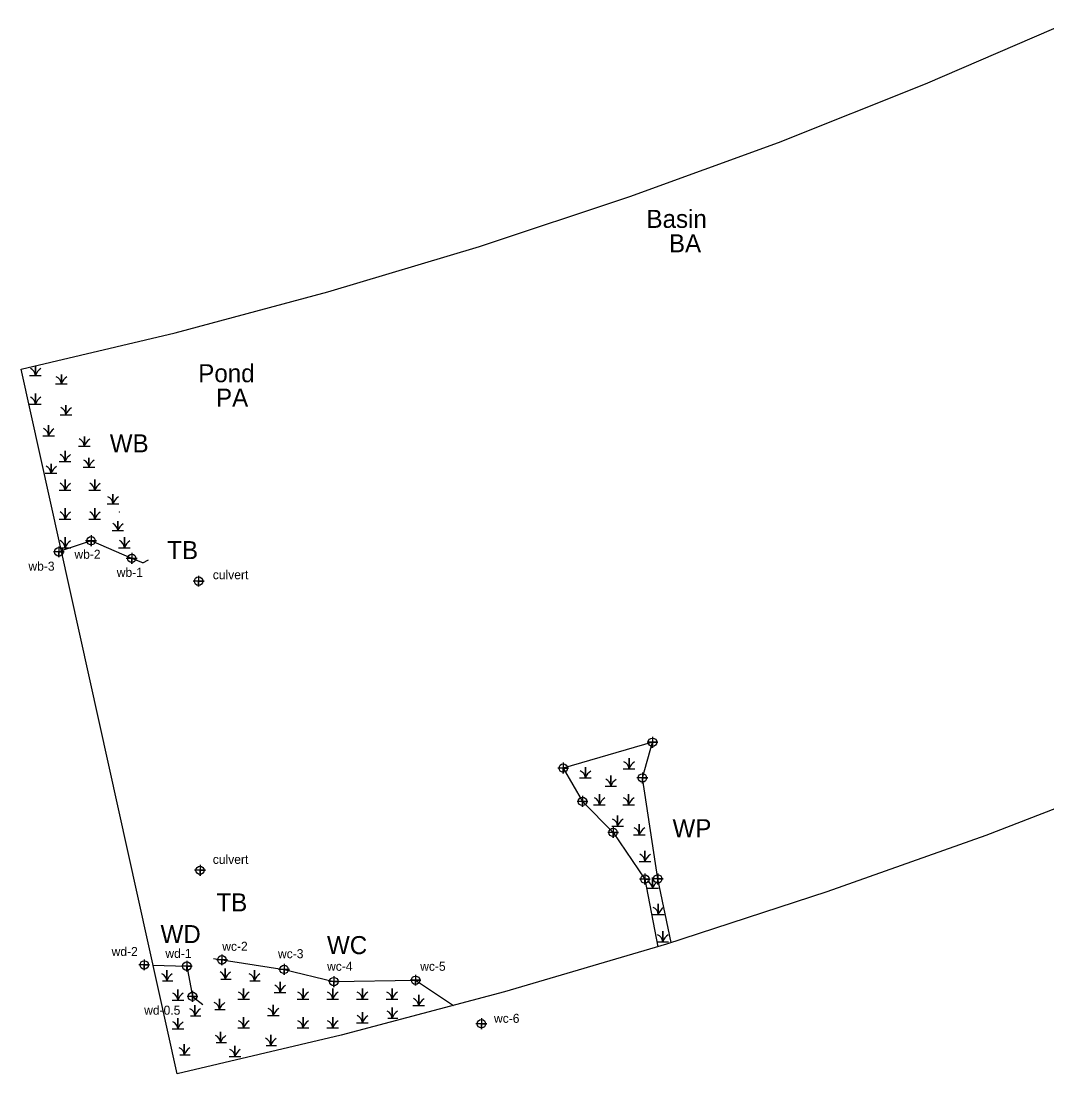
# Model space of a CAD drawing. Extents: x 2174810 to 2196950, y 76168 to 88270.
# Drawn here: x 2174810 to 2175379, y 76168 to 76752 of the extents above; entities that cross this region are included whole.
import ezdxf

# ---------------------------------------------------------------- set-up
doc = ezdxf.new("R2010")
doc.units = 0
for name, color, linetype in [('Default', 7, 'Continuous'), ('Exist Environmental Wetland Boundary', 7, 'Continuous'), ('Exist Environmental Wetland Boundary Cogo Number', 7, 'Continuous'), ('Exist Environmental Wetland Boundary Cogo Point CELL', 7, 'Continuous'), ('Exist Environmental Wetland Boundary Text', 7, 'Continuous'), ('Exist Hydro Jurisdictional Stream or Body of Water Mitigable Text', 7, 'Continuous'), ('Exist Hydro Jurisdictional Stream or Body of Water NonMitigable Cogo Number', 7, 'Continuous'), ('Exist Hydro Jurisdictional Stream or Body of Water NonMitigable Cogo Point CELL', 7, 'Continuous'), ('Exist Hydro Jurisdictional Stream or Body of Water NonMitigable Text', 7, 'Continuous'), ('Exist Hydro Swamp or Marsh', 7, 'Continuous')]:
    doc.layers.add(name, color=color, linetype=linetype)

msp = doc.modelspace()

# ---------------------------------------------------------------- linework, layer by layer
at = {"layer": 'Default'}
msp.add_lwpolyline([(2175432.71, 76334.2), (2175345.43, 76300.42), (2175257.26, 76269.05), (2175168.26, 76240.12), (2175078.5, 76213.66), (2174988.04, 76189.67), (2174896.96, 76168.18), (2174810.48, 76558.72), (2174895.85, 76578.94), (2174980.6, 76601.65), (2175064.65, 76626.82), (2175147.93, 76654.45), (2175230.37, 76684.5), (2175311.89, 76716.94), (2175392.42, 76751.76)], dxfattribs=at)
at = {"layer": 'Exist Environmental Wetland Boundary'}
for p, q in [((2174849.27, 76463.72), (2174832.77, 76458.03)), ((2174871.83, 76453.96), (2174849.27, 76463.72)), ((2174878, 76451.47), (2174871.83, 76453.96)), ((2174878, 76451.47), (2174881.16, 76453.17)), ((2174883.61, 76228.47), (2174902.38, 76227.91)), ((2174902.38, 76227.91), (2174905.52, 76211.18)), ((2174917.24, 76232.1), (2174956.29, 76226.14)), ((2174956.29, 76226.14), (2174983.88, 76219.34)), ((2174983.88, 76219.34), (2175029.2, 76220.11)), ((2175029.2, 76220.11), (2175050.3, 76206.18)), ((2174905.52, 76211.18), (2174911.31, 76206.67))]:
    msp.add_line(p, q, dxfattribs=at)
msp.add_lwpolyline([(2175170.83, 76240.96), (2175163.47, 76276.25), (2175154.94, 76332.25), (2175160.56, 76352), (2175111.07, 76337.73), (2175121.75, 76319.26), (2175138.71, 76302.08), (2175156.34, 76276.19), (2175163.49, 76238.72)], dxfattribs=at)
at = {"layer": 'Exist Environmental Wetland Boundary Cogo Point CELL'}
for points in [[(2174849.27, 76466.72), (2174849.27, 76460.72), (2174849.27, 76463.72), (2174852.27, 76463.72), (2174846.27, 76463.72)], [(2174831.41, 76460.56), (2174831.41, 76454.56), (2174831.41, 76457.56), (2174834.41, 76457.56), (2174828.41, 76457.56)], [(2174871.83, 76456.96), (2174871.83, 76450.96), (2174871.83, 76453.96), (2174874.83, 76453.96), (2174868.83, 76453.96)], [(2175160.56, 76355), (2175160.56, 76349), (2175160.56, 76352), (2175163.56, 76352), (2175157.56, 76352)], [(2175111.07, 76340.73), (2175111.07, 76334.73), (2175111.07, 76337.73), (2175114.07, 76337.73), (2175108.07, 76337.73)], [(2175154.94, 76335.25), (2175154.94, 76329.25), (2175154.94, 76332.25), (2175157.94, 76332.25), (2175151.94, 76332.25)], [(2175121.75, 76322.26), (2175121.75, 76316.26), (2175121.75, 76319.26), (2175124.75, 76319.26), (2175118.75, 76319.26)], [(2175138.71, 76305.08), (2175138.71, 76299.08), (2175138.71, 76302.08), (2175141.71, 76302.08), (2175135.71, 76302.08)], [(2175156.34, 76279.19), (2175156.34, 76273.19), (2175156.34, 76276.19), (2175159.34, 76276.19), (2175153.34, 76276.19)], [(2175163.47, 76279.25), (2175163.47, 76273.25), (2175163.47, 76276.25), (2175166.47, 76276.25), (2175160.47, 76276.25)], [(2174921.86, 76234.4), (2174921.86, 76228.4), (2174921.86, 76231.4), (2174924.86, 76231.4), (2174918.86, 76231.4)], [(2174878.77, 76231.62), (2174878.77, 76225.62), (2174878.77, 76228.62), (2174881.77, 76228.62), (2174875.77, 76228.62)], [(2174902.38, 76230.91), (2174902.38, 76224.91), (2174902.38, 76227.91), (2174905.38, 76227.91), (2174899.38, 76227.91)], [(2174956.29, 76229.14), (2174956.29, 76223.14), (2174956.29, 76226.14), (2174959.29, 76226.14), (2174953.29, 76226.14)], [(2174983.88, 76222.34), (2174983.88, 76216.34), (2174983.88, 76219.34), (2174986.88, 76219.34), (2174980.88, 76219.34)], [(2175029.2, 76223.11), (2175029.2, 76217.11), (2175029.2, 76220.11), (2175032.2, 76220.11), (2175026.2, 76220.11)], [(2174905.52, 76214.18), (2174905.52, 76208.18), (2174905.52, 76211.18), (2174908.52, 76211.18), (2174902.52, 76211.18)], [(2175065.69, 76199.02), (2175065.69, 76193.02), (2175065.69, 76196.02), (2175068.69, 76196.02), (2175062.69, 76196.02)]]:
    msp.add_lwpolyline(points, dxfattribs=at)
for centre in [(2174849.27, 76463.72), (2174831.41, 76457.56), (2174871.83, 76453.96), (2175160.56, 76352), (2175111.07, 76337.73), (2175154.94, 76332.25), (2175121.75, 76319.26), (2175138.71, 76302.08), (2175156.34, 76276.19), (2175163.47, 76276.25), (2174921.86, 76231.4), (2174878.77, 76228.62), (2174902.38, 76227.91), (2174956.29, 76226.14), (2174983.88, 76219.34), (2175029.2, 76220.11), (2174905.52, 76211.18), (2175065.69, 76196.02)]:
    msp.add_circle(centre, 2.34, dxfattribs=at)
at = {"layer": 'Exist Hydro Jurisdictional Stream or Body of Water NonMitigable Cogo Point CELL'}
for points in [[(2174908.92, 76444.3), (2174908.92, 76438.3), (2174908.92, 76441.3), (2174911.92, 76441.3), (2174905.92, 76441.3)], [(2174909.69, 76284.04), (2174909.69, 76278.04), (2174909.69, 76281.04), (2174912.69, 76281.04), (2174906.69, 76281.04)]]:
    msp.add_lwpolyline(points, dxfattribs=at)
for centre in [(2174908.92, 76441.3), (2174909.69, 76281.04)]:
    msp.add_circle(centre, 2.34, dxfattribs=at)
at = {"layer": 'Exist Hydro Swamp or Marsh'}
for p, q in [((2174921.07, 76185.57), (2174921.07, 76191.49)), ((2174921.07, 76191.49), (2174921.07, 76185.57)), ((2174918.61, 76185.57), (2174921.07, 76185.57)), ((2174921.07, 76185.57), (2174924.29, 76185.57))]:
    msp.add_line(p, q, dxfattribs=at)
for points in [[(2174815.23, 76555.35), (2174818.46, 76555.35), (2174818.46, 76560.61)], [(2174818.46, 76560.61), (2174818.46, 76555.35), (2174821.68, 76555.35)], [(2174829.62, 76550.66), (2174832.85, 76550.66), (2174832.85, 76555.92)], [(2174832.85, 76555.92), (2174832.85, 76550.66), (2174836.07, 76550.66)], [(2174815.23, 76539.43), (2174818.46, 76539.43), (2174818.46, 76545.35), (2174818.46, 76539.43), (2174821.68, 76539.43)], [(2174832.13, 76533.59), (2174835.36, 76533.59), (2174835.36, 76538.85)], [(2174835.36, 76538.85), (2174835.36, 76533.59), (2174838.58, 76533.59)], [(2174822.51, 76521.93), (2174825.73, 76521.93), (2174825.73, 76527.85), (2174825.73, 76521.93), (2174828.96, 76521.93)], [(2174842.34, 76516.18), (2174845.56, 76516.18), (2174845.56, 76521.44)], [(2174845.56, 76521.44), (2174845.56, 76516.18), (2174848.79, 76516.18)], [(2174831.68, 76507.59), (2174834.91, 76507.59), (2174834.91, 76513.51), (2174834.91, 76507.59), (2174838.14, 76507.59)], [(2174844.84, 76504.47), (2174848.07, 76504.47), (2174848.07, 76509.73)], [(2174848.07, 76509.73), (2174848.07, 76504.47), (2174851.3, 76504.47)], [(2174823.93, 76501.12), (2174827.16, 76501.12), (2174827.16, 76506.38)], [(2174827.16, 76506.38), (2174827.16, 76501.12), (2174830.38, 76501.12)], [(2174831.68, 76491.68), (2174834.91, 76491.68), (2174834.91, 76497.59), (2174834.91, 76491.68), (2174838.14, 76491.68)], [(2174848.14, 76491.68), (2174851.36, 76491.68), (2174851.36, 76497.59), (2174851.36, 76491.68), (2174854.59, 76491.68)], [(2174858.23, 76484.21), (2174861.45, 76484.21), (2174861.45, 76489.47)], [(2174861.45, 76489.47), (2174861.45, 76484.21), (2174864.68, 76484.21)], [(2174831.68, 76475.76), (2174834.91, 76475.76), (2174834.91, 76481.68), (2174834.91, 76475.76), (2174838.14, 76475.76)], [(2174848.14, 76475.76), (2174851.36, 76475.76), (2174851.36, 76481.68), (2174851.36, 76475.76), (2174854.59, 76475.76)], [(2174860.91, 76469.32), (2174864.13, 76469.32), (2174864.13, 76474.58)], [(2174864.13, 76474.58), (2174864.13, 76469.32), (2174867.36, 76469.32)], [(2174832.37, 76459.84), (2174834.91, 76459.84), (2174834.91, 76465.76), (2174834.91, 76459.84), (2174838.04, 76459.84)], [(2174864.59, 76459.84), (2174867.81, 76459.84), (2174867.81, 76465.76), (2174867.81, 76459.84), (2174871.04, 76459.84)], [(2175120.15, 76332.25), (2175123.38, 76332.25), (2175123.38, 76338.17), (2175123.38, 76332.25), (2175126.6, 76332.25)], [(2175144.32, 76337.3), (2175147.55, 76337.3), (2175147.55, 76343.22), (2175147.55, 76337.3), (2175150.77, 76337.3)], [(2175134.23, 76327.63), (2175137.46, 76327.63), (2175137.46, 76333.55), (2175137.46, 76327.63), (2175140.68, 76327.63)], [(2175127.93, 76317.33), (2175131.15, 76317.33), (2175131.15, 76323.24), (2175131.15, 76317.33), (2175134.38, 76317.33)], [(2175144.11, 76317.33), (2175147.34, 76317.33), (2175147.34, 76323.24), (2175147.34, 76317.33), (2175150.56, 76317.33)], [(2175138.02, 76305.55), (2175141.24, 76305.55), (2175141.24, 76311.47), (2175141.24, 76305.55), (2175144.47, 76305.55)], [(2175150, 76300.71), (2175153.22, 76300.71), (2175153.22, 76306.63), (2175153.22, 76300.71), (2175156.45, 76300.71)], [(2175153.15, 76285.99), (2175156.38, 76285.99), (2175156.38, 76291.91), (2175156.38, 76285.99), (2175159.6, 76285.99)], [(2175157.35, 76271.07), (2175160.58, 76271.07), (2175160.58, 76276.98), (2175160.58, 76271.07), (2175163.8, 76271.07)], [(2175160.51, 76256.56), (2175163.73, 76256.56), (2175163.73, 76262.47), (2175163.73, 76256.56), (2175166.96, 76256.56)], [(2175163.03, 76241.42), (2175166.25, 76241.42), (2175166.25, 76247.34), (2175166.25, 76241.42), (2175169.48, 76241.42)], [(2174888.85, 76219.8), (2174891.31, 76219.8), (2174891.31, 76225.72), (2174891.31, 76219.8), (2174894.54, 76219.8)], [(2174921.2, 76220.79), (2174923.66, 76220.79), (2174923.66, 76226.71), (2174923.66, 76220.79), (2174926.89, 76220.79)], [(2174937.38, 76219.8), (2174939.84, 76219.8), (2174939.84, 76225.72), (2174939.84, 76219.8), (2174943.07, 76219.8)], [(2174930.66, 76209.67), (2174933.89, 76209.67), (2174933.89, 76215.58), (2174933.89, 76209.67), (2174937.12, 76209.67)], [(2174950.83, 76213.38), (2174954.05, 76213.38), (2174954.05, 76219.3), (2174954.05, 76213.38), (2174957.28, 76213.38)], [(2174963.57, 76209.67), (2174966.79, 76209.67), (2174966.79, 76215.58), (2174966.79, 76209.67), (2174970.02, 76209.67)], [(2174980.02, 76209.67), (2174983.24, 76209.67), (2174983.24, 76215.58), (2174983.24, 76209.67), (2174986.47, 76209.67)], [(2174996.47, 76209.67), (2174999.69, 76209.67), (2174999.69, 76215.58), (2174999.69, 76209.67), (2175002.92, 76209.67)], [(2175012.92, 76209.67), (2175016.15, 76209.67), (2175016.15, 76215.58), (2175016.15, 76209.67), (2175019.37, 76209.67)], [(2174894.19, 76209.06), (2174897.41, 76209.06), (2174897.41, 76214.98), (2174897.41, 76209.06), (2174900.64, 76209.06)], [(2174917.99, 76203.86), (2174920.45, 76203.86), (2174920.45, 76209.78), (2174920.45, 76203.86), (2174923.68, 76203.86)], [(2175027.7, 76206.03), (2175030.93, 76206.03), (2175030.93, 76211.95), (2175030.93, 76206.03), (2175034.16, 76206.03)], [(2174904.41, 76200.4), (2174906.86, 76200.4), (2174906.86, 76206.32), (2174906.86, 76200.4), (2174910.09, 76200.4)], [(2174947.12, 76200.57), (2174950.34, 76200.57), (2174950.34, 76206.49), (2174950.34, 76200.57), (2174953.57, 76200.57)], [(2175013.76, 76199.11), (2175016.21, 76199.11), (2175016.21, 76205.03), (2175016.21, 76199.11), (2175019.44, 76199.11)], [(2174894.19, 76193.14), (2174897.41, 76193.14), (2174897.41, 76199.06), (2174897.41, 76193.14), (2174900.64, 76193.14)], [(2174930.66, 76193.75), (2174933.89, 76193.75), (2174933.89, 76199.67), (2174933.89, 76193.75), (2174937.12, 76193.75)], [(2174963.57, 76193.75), (2174966.79, 76193.75), (2174966.79, 76199.67), (2174966.79, 76193.75), (2174970.02, 76193.75)], [(2174980.02, 76193.75), (2174983.24, 76193.75), (2174983.24, 76199.67), (2174983.24, 76193.75), (2174986.47, 76193.75)], [(2174996.47, 76196.55), (2174999.69, 76196.55), (2174999.69, 76202.47), (2174999.69, 76196.55), (2175002.92, 76196.55)], [(2174946.44, 76183.99), (2174948.9, 76183.99), (2174948.9, 76189.91), (2174948.9, 76183.99), (2174952.12, 76183.99)], [(2174898.53, 76178.82), (2174900.99, 76178.82), (2174900.99, 76184.73), (2174900.99, 76178.82), (2174904.22, 76178.82)], [(2174925.82, 76177.83), (2174929.04, 76177.83), (2174929.04, 76183.75), (2174929.04, 76177.83), (2174932.27, 76177.83)]]:
    msp.add_lwpolyline(points, dxfattribs=at)
for centre, radius, start, end in [((2174813.86, 76555.01), 4.61, 4.14034, 67.53497), ((2174825.3, 76553.08), 7.21, 122.12745, 161.62219), ((2174828.25, 76550.33), 4.61, 4.14034, 67.53497), ((2174839.69, 76548.39), 7.21, 122.12745, 161.62219), ((2174813.86, 76539.1), 4.61, 4.14034, 67.53497), ((2174825.3, 76537.16), 7.21, 122.12745, 161.62219), ((2174830.76, 76533.26), 4.61, 4.14034, 67.53497), ((2174842.2, 76531.32), 7.21, 122.12745, 161.62219), ((2174821.13, 76521.6), 4.61, 4.14034, 67.53497), ((2174832.57, 76519.66), 7.21, 122.12745, 161.62219), ((2174840.96, 76515.85), 4.61, 4.14034, 67.53497), ((2174852.4, 76513.91), 7.21, 122.12745, 161.62219), ((2174830.31, 76507.26), 4.61, 4.14034, 67.53497), ((2174841.75, 76505.32), 7.21, 122.12745, 161.62219), ((2174843.47, 76504.13), 4.61, 4.14034, 67.53497), ((2174854.91, 76502.19), 7.21, 122.12745, 161.62219), ((2174822.56, 76500.78), 4.61, 4.14034, 67.53497), ((2174834, 76498.84), 7.21, 122.12745, 161.62219), ((2174830.31, 76491.34), 4.61, 4.14034, 67.53497), ((2174841.75, 76489.4), 7.21, 122.12745, 161.62219), ((2174846.76, 76491.34), 4.61, 4.14034, 67.53497), ((2174858.2, 76489.4), 7.21, 122.12745, 161.62219), ((2174856.85, 76483.88), 4.61, 4.14034, 67.53497), ((2174868.3, 76481.94), 7.21, 122.12745, 161.62219), ((2174830.31, 76475.43), 4.61, 4.14034, 67.53497), ((2174841.75, 76473.49), 7.21, 122.12745, 161.62219), ((2174846.76, 76475.43), 4.61, 4.14034, 67.53497), ((2174858.2, 76473.49), 7.21, 122.12745, 161.62219), ((2174863.21, 76475.43), 4.61, 64.43035, 67.53497), ((2174859.53, 76468.98), 4.61, 4.14034, 67.53497), ((2174870.97, 76467.04), 7.21, 122.12745, 161.62219), ((2174830.31, 76459.51), 4.61, 4.14034, 67.53497), ((2174841.75, 76457.57), 7.21, 122.12745, 161.62219), ((2174863.21, 76459.51), 4.61, 4.14034, 67.53497), ((2174874.65, 76457.57), 7.21, 122.12745, 161.62219), ((2175142.95, 76336.97), 4.61, 4.14034, 67.53497), ((2175154.39, 76335.03), 7.21, 122.12745, 161.62219), ((2175118.78, 76331.92), 4.61, 4.14034, 67.53497), ((2175130.22, 76329.98), 7.21, 122.12745, 161.62219), ((2175132.86, 76327.3), 4.61, 4.14034, 67.53497), ((2175144.3, 76325.36), 7.21, 122.12745, 161.62219), ((2175126.55, 76316.99), 4.61, 4.14034, 67.53497), ((2175137.99, 76315.05), 7.21, 122.12745, 161.62219), ((2175142.74, 76316.99), 4.61, 4.14034, 67.53497), ((2175154.18, 76315.05), 7.21, 122.12745, 161.62219), ((2175136.64, 76305.22), 4.61, 4.14034, 67.53497), ((2175148.08, 76303.28), 7.21, 122.12745, 161.62219), ((2175148.62, 76300.38), 4.61, 4.14034, 67.53497), ((2175160.06, 76298.44), 7.21, 122.12745, 161.62219), ((2175151.78, 76285.66), 4.61, 4.14034, 67.53497), ((2175163.22, 76283.72), 7.21, 122.12745, 161.62219), ((2175155.98, 76270.73), 4.61, 4.14034, 67.53497), ((2175167.42, 76268.79), 7.21, 122.12745, 161.62219), ((2175159.13, 76256.22), 4.61, 4.14034, 67.53497), ((2175170.57, 76254.28), 7.21, 122.12745, 161.62219), ((2175161.65, 76241.08), 4.61, 4.14034, 67.53497), ((2175173.09, 76239.14), 7.21, 122.12745, 161.62219), ((2174886.71, 76219.47), 4.61, 4.14034, 67.53497), ((2174898.15, 76217.53), 7.21, 122.12745, 161.62219), ((2174919.06, 76220.46), 4.61, 4.14034, 67.53497), ((2174930.5, 76218.52), 7.21, 122.12745, 161.62219), ((2174935.24, 76219.47), 4.61, 4.14034, 67.53497), ((2174946.68, 76217.53), 7.21, 122.12745, 161.62219), ((2174949.45, 76213.05), 4.61, 4.14034, 67.53497), ((2174960.89, 76211.11), 7.21, 122.12745, 161.62219), ((2174892.81, 76208.73), 4.61, 4.14034, 67.53497), ((2174904.25, 76206.79), 7.21, 122.12745, 161.62219), ((2174929.29, 76209.33), 4.61, 4.14034, 67.53497), ((2174940.73, 76207.39), 7.21, 122.12745, 161.62219), ((2174962.19, 76209.33), 4.61, 4.14034, 67.53497), ((2174973.63, 76207.39), 7.21, 122.12745, 161.62219), ((2174978.64, 76209.33), 4.61, 4.14034, 67.53497), ((2174990.08, 76207.39), 7.21, 122.12745, 161.62219), ((2174995.09, 76209.33), 4.61, 4.14034, 67.53497), ((2175006.54, 76207.39), 7.21, 122.12745, 161.62219), ((2175011.55, 76209.33), 4.61, 4.14034, 67.53497), ((2175022.99, 76207.39), 7.21, 122.12745, 161.62219), ((2175026.33, 76205.7), 4.61, 4.14034, 67.53497), ((2175037.77, 76203.76), 7.21, 122.12745, 161.62219), ((2174902.27, 76200.07), 4.61, 4.14034, 67.53497), ((2174913.71, 76198.13), 7.21, 122.12745, 161.62219), ((2174915.85, 76203.53), 4.61, 4.14034, 67.53497), ((2174927.29, 76201.59), 7.21, 122.12745, 161.62219), ((2174945.74, 76200.24), 4.61, 4.14034, 67.53497), ((2174957.18, 76198.3), 7.21, 122.12745, 161.62219), ((2174929.29, 76193.42), 4.61, 4.14034, 67.53497), ((2174962.19, 76193.42), 4.61, 4.14034, 67.53497), ((2174978.64, 76193.42), 4.61, 4.14034, 67.53497), ((2174995.09, 76196.22), 4.61, 4.14034, 67.53497), ((2175006.54, 76194.28), 7.21, 122.12745, 161.62219), ((2175011.61, 76198.78), 4.61, 4.14034, 67.53497), ((2175023.05, 76196.84), 7.21, 122.12745, 161.62219), ((2174892.81, 76192.81), 4.61, 4.14034, 67.53497), ((2174904.25, 76190.87), 7.21, 122.12745, 161.62219), ((2174940.73, 76191.48), 7.21, 122.12745, 161.62219), ((2174973.63, 76191.48), 7.21, 122.12745, 161.62219), ((2174990.08, 76191.48), 7.21, 122.12745, 161.62219), ((2174916.47, 76185.24), 4.61, 4.14034, 67.53497), ((2174927.91, 76183.3), 7.21, 122.12745, 161.62219), ((2174944.3, 76183.66), 4.61, 4.14034, 67.53497), ((2174955.74, 76181.72), 7.21, 122.12745, 161.62219), ((2174896.39, 76178.48), 4.61, 4.14034, 67.53497), ((2174907.83, 76176.54), 7.21, 122.12745, 161.62219), ((2174924.44, 76177.5), 4.61, 4.14034, 67.53497), ((2174935.88, 76175.56), 7.21, 122.12745, 161.62219)]:
    msp.add_arc(centre, radius, start, end, dxfattribs=at)

# ---------------------------------------------------------------- texts
at = {"layer": 'Exist Environmental Wetland Boundary Cogo Number'}
for s, p in [('wb-2', (2174840.07, 76453.72)), ('wb-3', (2174814.56, 76447.11)), ('wb-1', (2174863.54, 76443.7)), ('wd-2', (2174860.69, 76233.54)), ('wc-2', (2174922.01, 76236.43)), ('wd-1', (2174890.49, 76232.48)), ('wc-3', (2174952.92, 76232.33)), ('wc-4', (2174980.15, 76225.35)), ('wc-5', (2175031.76, 76225.35)), ('wd-0.5', (2174878.73, 76201.01)), ('wc-6', (2175072.68, 76196.51))]:
    msp.add_text(s, height=5, dxfattribs=at).set_placement(p)
at = {"layer": 'Exist Environmental Wetland Boundary Text'}
for s, p in [('WB', (2174859.67, 76512.71)), ('WP', (2175171.66, 76299.39)), ('WD', (2174887.81, 76240.69)), ('WC', (2174980.1, 76234.59))]:
    msp.add_text(s, height=10, dxfattribs=at).set_placement(p)
at = {"layer": 'Exist Hydro Jurisdictional Stream or Body of Water Mitigable Text'}
for s, p in [('Pond', (2174908.72, 76551.57)), ('PA', (2174918.57, 76538.03))]:
    msp.add_text(s, height=10, dxfattribs=at).set_placement(p)
at = {"layer": 'Exist Hydro Jurisdictional Stream or Body of Water NonMitigable Cogo Number'}
for p in [(2174916.78, 76442.37), (2174916.78, 76284.6)]:
    msp.add_text('culvert', height=5, dxfattribs=at).set_placement(p)
at = {"layer": 'Exist Hydro Jurisdictional Stream or Body of Water NonMitigable Text'}
for s, p in [('Basin', (2175157.23, 76637.12)), ('BA', (2175169.67, 76623.58)), ('TB', (2174891.53, 76453.51)), ('TB', (2174918.79, 76258.27))]:
    msp.add_text(s, height=10, dxfattribs=at).set_placement(p)

doc.saveas('drawing.dxf')
